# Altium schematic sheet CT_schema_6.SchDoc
size 277 x 170 mm
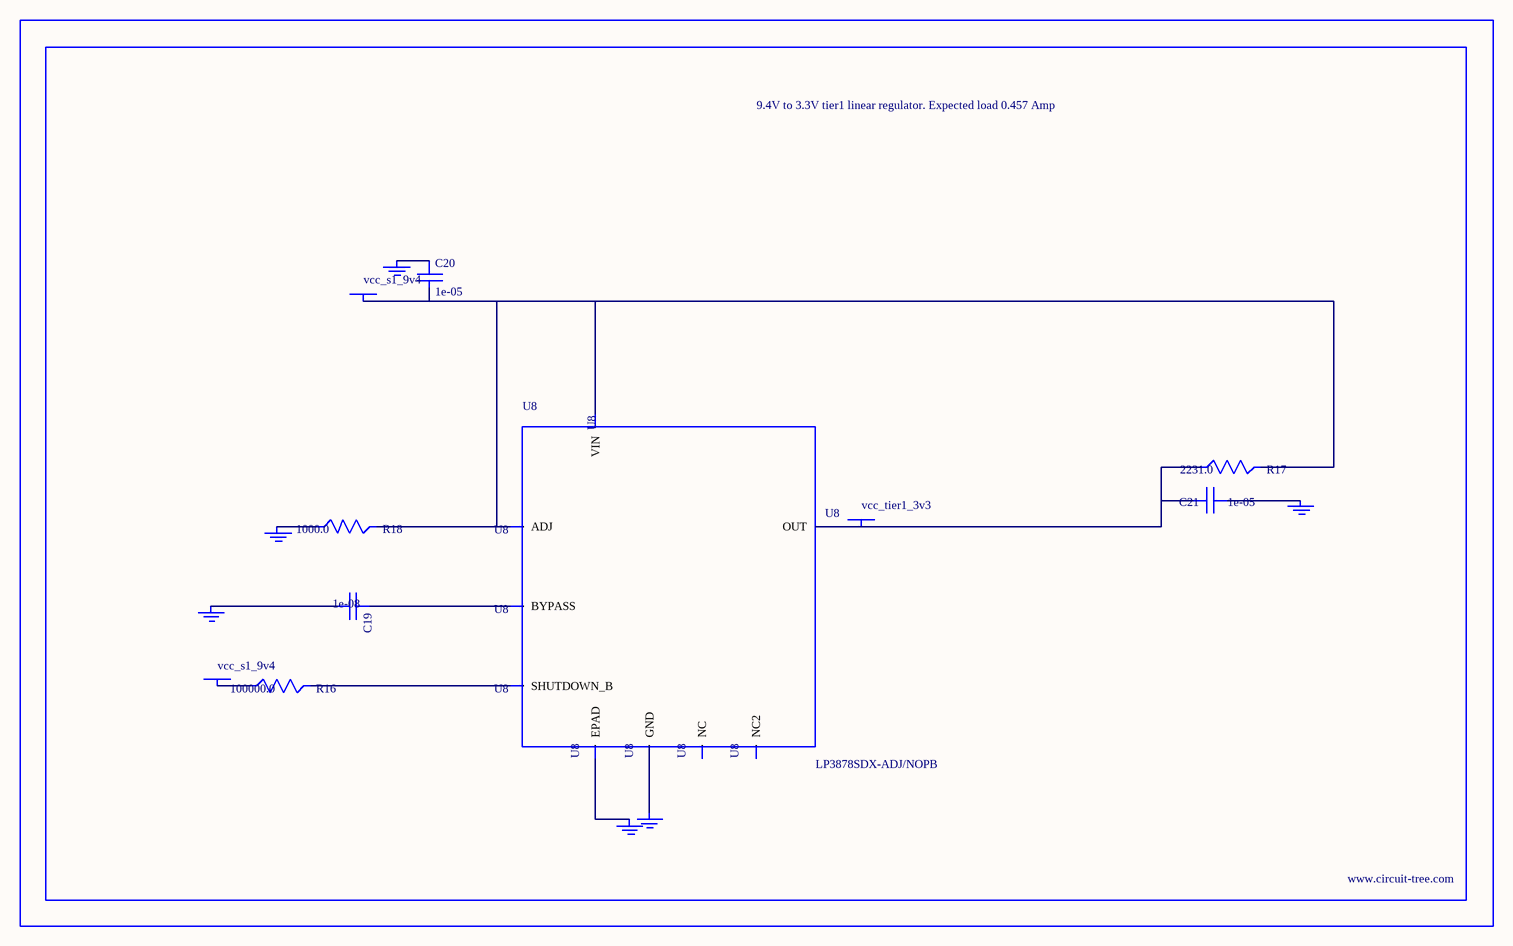
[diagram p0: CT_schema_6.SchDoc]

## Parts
BORDER5  (no value)
C19  1e-08  [C0402]
C20  1e-05  [C1206]
C21  1e-05  [C1210]
GND_INSTANCE_5_0  (no value)
GND_INSTANCE_5_1  (no value)
GND_INSTANCE_5_2  (no value)
GND_INSTANCE_5_3  (no value)
GND_INSTANCE_5_4  (no value)
GND_INSTANCE_5_5  (no value)
POWER_INSTANCE_5_0  vcc_s1_9v4
POWER_INSTANCE_5_1  vcc_s1_9v4
POWER_INSTANCE_5_2  vcc_tier1_3v3
R16  100000.0  [R0603]
R17  2231.0  [R0603]
R18  1000.0  [R0603]
U8  LP3878SDX-ADJ/NOPB  [WSON-8]

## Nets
NetC19_1: C19.1 U8.1(BYPASS)
NetC19_2: C19.2 GND_INSTANCE_5_0.0(GND)
NetC20_1: C20.1 GND_INSTANCE_5_1.0(GND)
NetC20_2: C20.2 POWER_INSTANCE_5_0.0(PWR) R17.2 R18.2 U8.4(VIN) U8.6(ADJ)
NetC21_1: C21.1 GND_INSTANCE_5_2.0(GND)
NetC21_2: C21.2 POWER_INSTANCE_5_2.0(PWR) R17.1 U8.5(OUT)
NetGND_INSTANCE_5_3_0: GND_INSTANCE_5_3.0(GND) R18.1
NetGND_INSTANCE_5_4_0: GND_INSTANCE_5_4.0(GND) U8.PAD(EPAD)
NetGND_INSTANCE_5_5_0: GND_INSTANCE_5_5.0(GND) U8.3(GND)
NetPOWER_INSTANCE_5_1_0: POWER_INSTANCE_5_1.0(PWR) R16.1
NetR16_2: R16.2 U8.8(SHUTDOWN_B)

Not connected (* = marked no-connect by the designer): U8 2(NC) 7(NC2)

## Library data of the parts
BORDER5 = BORDER_PAGE5
C19 = C0402C103K3RAC
C20 = C1206C106K3RACTU
C21 = GRM32DR61E106MA12L
GND_INSTANCE_5_0-GND_INSTANCE_5_5 = GND
POWER_INSTANCE_5_0-POWER_INSTANCE_5_2 = PWR
R16 = RC0603JR-07100KL
R17 = R17
R18 = RC0603JR-071KL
